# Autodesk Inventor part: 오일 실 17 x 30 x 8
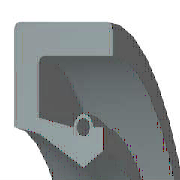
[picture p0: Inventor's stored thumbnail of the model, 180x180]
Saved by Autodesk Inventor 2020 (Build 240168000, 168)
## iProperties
Created: 2012-02
Part Number: 오일 실 17 x 30 x 8
Material: 고무
Description: 오일 실 - 스프링 장착, 금속 케이스 SM
Document SubType Name: Modeling
Standard: JIS B 2402
Designer: mdu-01
Standards Organization: JIS
Language: ko-KR
Size Designation: 17 30 8 A
Categories: <MemberInstance><Categories><Category DisplayName="샤프트 부품" InternalName="7f7aeb1f-a693-4053-b835-cee3144e0d98" Mnemonic="SHFT"><Category DisplayName="실링" Intern
Density: 0.93 g/cm^3
Appearance: Rubber-Black
IsCustomPart: 1
Author: mdu-01
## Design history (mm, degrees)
body "Solid1"
revolve "회전1" stored, may be unused: angle "d33" = 360 deg
fillet "모깎기1" dims "d34" = 0.4 (= 0.05 x b)
chamfer "모따기1" distance "d35" = 0.8 (= 0.1 x b); stored, may be unused: second distance "d36" = 0.4 (= 0.05 x b), angle "d41" = 45 deg
sketch "스케치2"
  geometry: L1 (10.079, -5.895)-(10.689, -8); L2 (9.429, -5.2)-(10.079, -5.895); L3 (8.5, -2)-(9.429, -5.2); L4 (9.367, -1)-(8.5, -2); L5 (10.819, -1)-(9.367, -1); L6 (10.819, -1.8)-(10.819, -1); L7 (10.819, -6)-(10.819, -3.4); L8 (12.4, -6)-(10.819, -6); L9 (13.7, -2)-(12.4, -6); L10 (13.7, 0)-(13.7, -2); L11 (15, 0)-(13.7, 0); L12 (15, -8)-(15, 0); L13 (10.689, -8)-(15, -8); L14 (0, -9.6)-(0, 1.6) reference; L15 (28, 0)-(14, 0) reference; A1 r 0.8 centre (10.819, -2.6) between (10.819, -3.4) and (10.819, -1.8)
  constraints: 26 end point, 4 horizontal, 4 vertical, 2 point on circle, 1 centre point, 1 collinear, 1 parallel
  dimensions: "d2" = 8 distance of L12.start L11.start (= b); "d4" = 1 vertical distance of L10.start L5.start (= 0.125 x b); "d6" = 1.3 distance of L11.start L10.start (= 0.1 x dd - 0.1 x Diam); "d8" = 2 distance of L10.start L9.start (= 0.25 x b); "d10" = 2 vertical distance of L8.start L1.end (= 0.25 x b); "d12" = 1.3 horizontal distance of L9.start L8.start (= 0.1 x dd - 0.1 x Diam); "d14" = 0.8 radius of A1 (= 0.1 x b); "d16" = 0 horizontal distance of A1.centre L7.end; "d18" = 0.8 distance of L6.start L5.start (= 0.1 x b); "d20" = 0.86667 horizontal distance of L4.start L3.start (= 0.0666667 x dd - 0.0666667 x Diam); "d22" = 0.13 horizontal distance of L7.start L1.end (= 0.01 x dd - 0.01 x Diam); "d24" = 1 vertical distance of L4.start L3.start (= 0.125 x b); "d26" = 3.2 vertical distance of L3.start L2.start (= 0.4 x b); "d28" = 0.92857 horizontal distance of L3.start L2.start (= 0.0714286 x dd - 0.0714286 x Diam); "d30" = 2.10526 vertical distance of L1.start L1.end (= 0.263158 x b); "d32" = 0.65 horizontal distance of L2.start L1.start (= 0.05 x dd - 0.05 x Diam); "d37" = 0 distance between parallel lines of L15 L11; "d38" = 15 distance between parallel lines of L14 L12 (= 0.5 x dd); "d39" = 8.5 distance from line of L14 L3.start (= 0.5 x Diam)
other parameters: "Diam" = 17 [user parameter; used in 7 equation terms], "b" = 8 [user parameter; used in 12 equation terms], "d1" = 8 (derived), "d3" = 1 (derived), "d5" = 2 (derived), "d7" = 2 (derived), "d9" = 2 (derived), "d11" = 2 (derived), "d13" = 0.8 (derived), "d15" = 0 (derived), "d17" = 0.8 (derived), "d19" = 1.33333 (derived), "d21" = 0.2 (derived), "d23" = 1 (derived), "d25" = 3.2 (derived), "d27" = 1.42857 (derived), "d29" = 2.10526 (derived), "d31" = 1 (derived), "d40" = 0
